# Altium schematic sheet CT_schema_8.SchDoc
size 277 x 170 mm
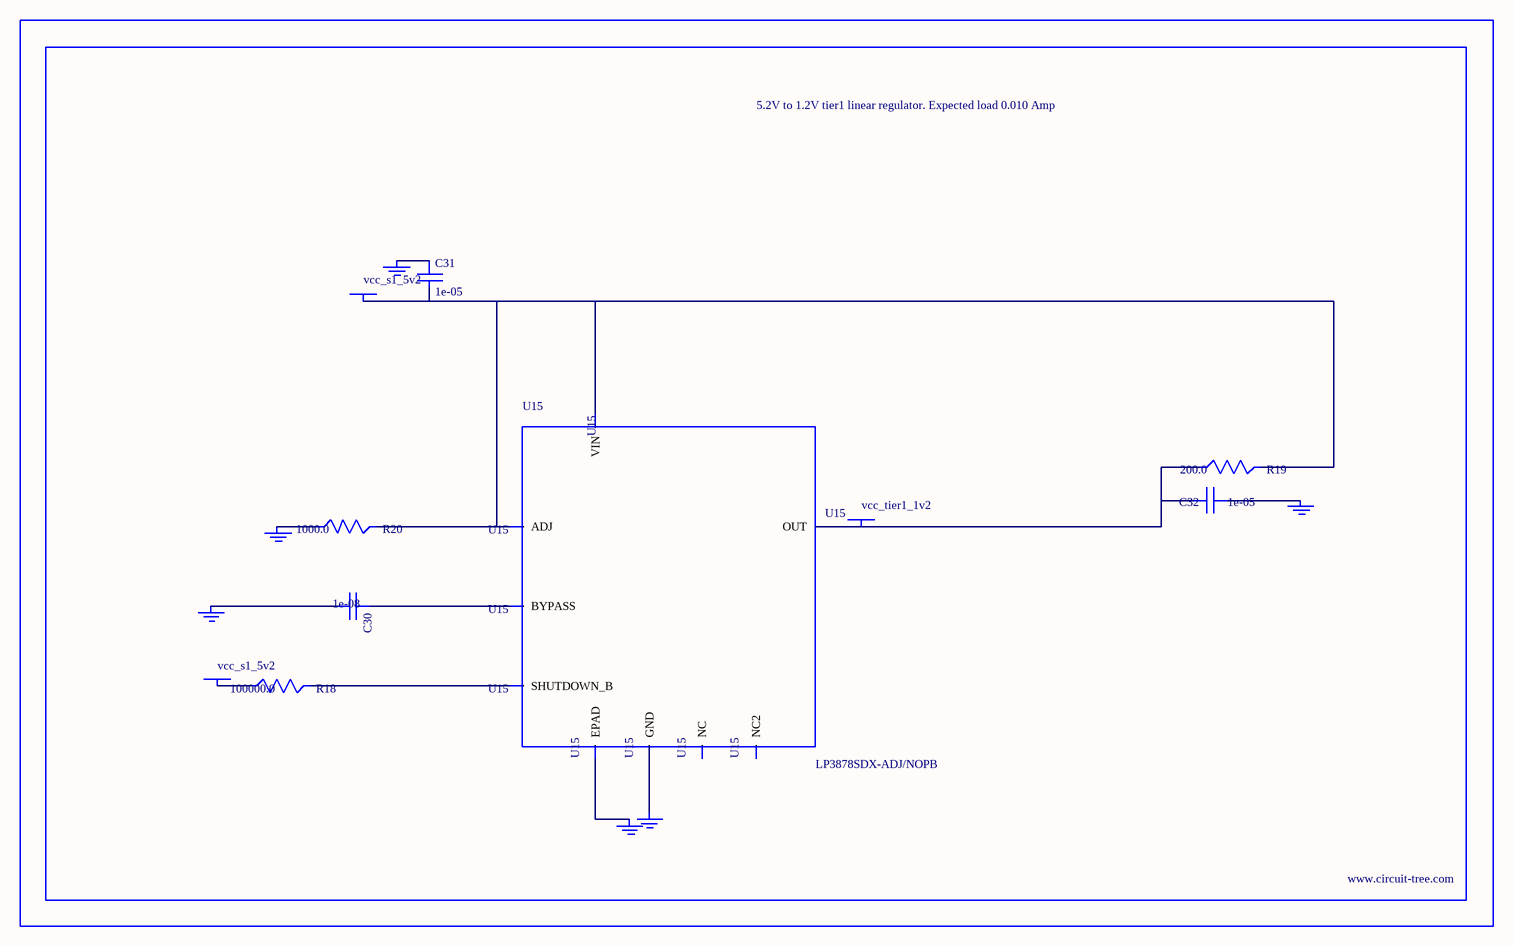
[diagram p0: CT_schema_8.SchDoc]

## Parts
BORDER7  (no value)
C30  1e-08  [C0402]
C31  1e-05  [C1206]
C32  1e-05  [C0805]
GND_INSTANCE_7_0  (no value)
GND_INSTANCE_7_1  (no value)
GND_INSTANCE_7_2  (no value)
GND_INSTANCE_7_3  (no value)
GND_INSTANCE_7_4  (no value)
GND_INSTANCE_7_5  (no value)
POWER_INSTANCE_7_0  vcc_s1_5v2
POWER_INSTANCE_7_1  vcc_s1_5v2
POWER_INSTANCE_7_2  vcc_tier1_1v2
R18  100000.0  [R0603]
R19  200.0  [R0603]
R20  1000.0  [R0603]
U15  LP3878SDX-ADJ/NOPB  [WSON-8]

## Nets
NetC30_1: C30.1 U15.1(BYPASS)
NetC30_2: C30.2 GND_INSTANCE_7_0.0(GND)
NetC31_1: C31.1 GND_INSTANCE_7_1.0(GND)
NetC31_2: C31.2 POWER_INSTANCE_7_0.0(PWR) R19.2 R20.2 U15.4(VIN) U15.6(ADJ)
NetC32_1: C32.1 GND_INSTANCE_7_2.0(GND)
NetC32_2: C32.2 POWER_INSTANCE_7_2.0(PWR) R19.1 U15.5(OUT)
NetGND_INSTANCE_7_3_0: GND_INSTANCE_7_3.0(GND) R20.1
NetGND_INSTANCE_7_4_0: GND_INSTANCE_7_4.0(GND) U15.PAD(EPAD)
NetGND_INSTANCE_7_5_0: GND_INSTANCE_7_5.0(GND) U15.3(GND)
NetPOWER_INSTANCE_7_1_0: POWER_INSTANCE_7_1.0(PWR) R18.1
NetR18_2: R18.2 U15.8(SHUTDOWN_B)

Not connected (* = marked no-connect by the designer): U15 2(NC) 7(NC2)

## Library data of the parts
BORDER7 = BORDER_PAGE7
C30 = C0402C103K3RAC
C31 = C1206C106K3RACTU
C32 = GRM219R60J106ME19D
GND_INSTANCE_7_0-GND_INSTANCE_7_5 = GND
POWER_INSTANCE_7_0-POWER_INSTANCE_7_2 = PWR
R18 = RC0603JR-07100KL
R19 = RC0603JR-07200RL
R20 = RC0603JR-071KL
